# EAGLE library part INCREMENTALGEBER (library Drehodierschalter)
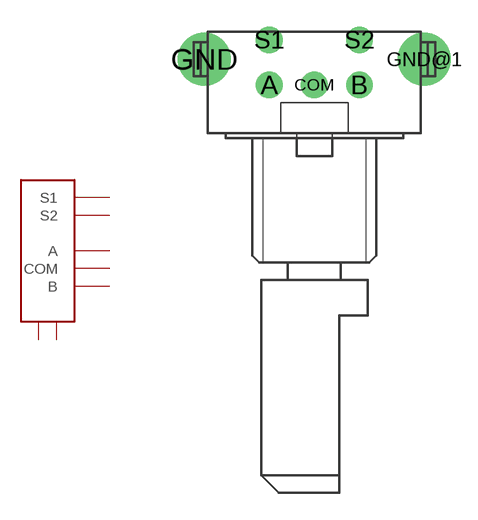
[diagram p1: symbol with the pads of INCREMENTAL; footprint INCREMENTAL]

Designator prefix S

## INCREMENTALGEBER  [INCREMENTAL]
A  A
B  B
COM  COM
GND  M
GND@1  M
S1  S1
S2  S2

## Footprint INCREMENTAL (pad centres in mm)
drill 1 round: A -2.54,0; B 2.54,0; COM 0,0; S1 -2.54,2.54; S2 2.54,2.54
drill 2 round: GND -6.2,1.45; GND@1 6.2,1.45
